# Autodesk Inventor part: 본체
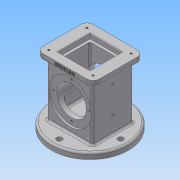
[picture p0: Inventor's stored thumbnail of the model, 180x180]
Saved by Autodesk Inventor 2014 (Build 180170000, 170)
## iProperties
Created: 2018-10
Part Number: 본체
Material: Generic
Document SubType Name: Modeling
Designer: Administrator
Density: 1 g/cm^3
Appearance: Default
Author: Administrator
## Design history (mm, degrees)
sketch "스케치1"
  geometry: C1 r 62.5 at (0, 0); 1 further point
  constraints: 1 centre point, 1 coincident
  dimensions: "d0" = 125 diameter of C1
extrude "돌출1" new body sketch "스케치1" distance "d1" = 10; taper "d2" = 0 deg
sketch "스케치2"
  geometry: L1 (-37, 33)-(37, 33); L2 (37, 33)-(37, -33); L3 (37, -33)-(-37, -33); L4 (-37, -33)-(-37, 33); L5 (-37, 33)-(37, -33); L6 (37, 33)-(-37, -33); C1 r 62.5 at (0, 0) reference
  constraints: 12 end point, 2 midpoint, 2 parallel, 1 horizontal, 1 perpendicular
  dimensions: "d3" = 74 distance of L2.end L3.end; "d4" = 66 distance of L1.end L2.end
extrude "돌출2" join sketch "스케치2" distance "d5" = 98; taper "d6" = 0 deg
sketch "스케치3"
  geometry: L1 (37, 33)-(-37, 33) reference; L2 (-37, 33)-(-37, -33) reference; L3 (-37, -33)-(37, -33) reference; L4 (37, -33)-(37, 33) reference; L5 (-46, 41)-(46, 41); L6 (46, 41)-(46, -41); L7 (46, -41)-(-46, -41); L8 (-46, -41)-(-46, 41); L9 (-46, 41)-(46, -41); L10 (46, 41)-(-46, -41); 1 further point
  constraints: 12 end point, 2 midpoint, 2 parallel, 1 horizontal, 1 perpendicular
  dimensions: "d7" = 92 distance of L6.end L7.end; "d8" = 82 distance of L5.end L6.end
extrude "돌출3" join sketch "스케치3" distance "d9" = 10; taper "d10" = 0 deg
sketch "스케치6"
  geometry: L1 (-25.5, -10)-(99.5, -10) reference; C1 r 35 at (37, 44); 2 further points
  constraints: 1 centre point, 1 midpoint, 1 vertical alignment
  dimensions: "d19" = 70 diameter of C1; "d20" = 54 distance from line of L1 C1.centre
extrude "돌출6" cut sketch "스케치6" distance "d21" = 3; taper "d22" = 0 deg
sketch "스케치7"
  geometry: C1 r 35 at (0, 0) reference; C2 r 24 at (0, 0); 1 further point
  constraints: 1 centre point, 1 coincident
  dimensions: "d23" = 48 diameter of C2
extrude "돌출7" cut sketch "스케치7" stored distance "d24" = 10; taper "d25" = 0 deg
sketch "스케치8"
  geometry: L1 (-26, 26)-(26, 26); L2 (26, 26)-(26, -26); L3 (26, -26)-(-26, -26); L4 (-26, -26)-(-26, 26); L5 (-26, 26)-(26, -26); L6 (26, 26)-(-26, -26); 1 further point
  constraints: 12 end point, 2 midpoint, 2 parallel, 1 horizontal, 1 perpendicular
  dimensions: "d26" = 52 distance of L2.end L3.end; "d27" = 52 distance of L1.end L2.end
extrude "돌출8" cut sketch "스케치8" distance "d28" = 8; taper "d29" = 0 deg
sketch "스케치9"
  geometry: L1 (-22, 22)-(22, 22); L2 (22, 22)-(22, -22); L3 (22, -22)-(-22, -22); L4 (-22, -22)-(-22, 22); L5 (-22, 22)-(22, -22); L6 (22, 22)-(-22, -22); 1 further point
  constraints: 12 end point, 2 midpoint, 2 parallel, 1 horizontal, 1 perpendicular
  dimensions: "d30" = 44 distance of L2.end L3.end; "d31" = 44 distance of L1.end L2.end
extrude "돌출9" cut sketch "스케치9" distance "d32" = 74; taper "d33" = 0 deg
sketch "스케치10"
  geometry: L1 (0, 0)-(-28, 0); L2 (-28, 0)-(-24.874, 17.727); L3 (-24.874, 17.727)-(0, 17.727); L4 (0, 17.727)-(0, 0)
  constraints: 8 end point, 1 horizontal, 1 parallel, 1 perpendicular
  dimensions: "d34" = 28 distance of L1.start L1.end; "d35" = 18 distance of L1.end L2.end; "d36" = 80 deg angle of L1 L2
revolve "회전1" sketch "스케치10" stored, may be unused: angle "d37" = 90 deg
fillet "모깎기1" dims "d38" = 3
fillet "모깎기2" dims "d39" = 3
fillet "모깎기3" dims "d40" = 3
fillet "모깎기4" dims "d41" = 10
fillet "모깎기5" dims "d42" = 3
chamfer "모따기1" distance "d43" = 1; stored, may be unused: second distance "d44" = 2, angle "d45" = 45 deg
fillet "모깎기6" dims "d46" = 3
fillet "모깎기7" dims "d47" = 3
fillet "모깎기8" dims "d48" = 3
fillet "모깎기9" dims "d49" = 3
sketch "스케치11"
  geometry: A1 r 10 centre (-36, 31) between (-36, 41) and (-46, 31) reference; A2 r 10 centre (-36, -31) between (-46, -31) and (-36, -41) reference; A3 r 10 centre (36, -31) between (36, -41) and (46, -31) reference; A4 r 10 centre (36, 31) between (46, 31) and (36, 41) reference; 5 further points
  constraints: 4 coincident
hole "구멍1" sketch "스케치11" at (-36, 31), (36, 31), (36, -31), (-36, -31) diameter "d50" = 3.242; stored, may be unused: countersink angle "d54" = 90 deg, drill point angle "d56" = 118 deg; dims "d51" = 4, "d52" = 4, "d53" = 2, "d55" = 6
sketch "스케치12"
  geometry: C1 r 24 at (0, 0) reference; 2 further points
  constraints: 1 vertical alignment
  dimensions: "d57" = 29 distance of C1.centre point (0, 29)
hole "구멍2" sketch "스케치12" at (0, 29) diameter "d58" = 3.242; stored, may be unused: countersink angle "d62" = 90 deg, drill point angle "d64" = 118 deg; dims "d59" = 4, "d60" = 4, "d61" = 2, "d63" = 6
node "작업축1"
sketch "스케치13"
  geometry: L1 (13, -32.5)-(13, 92.5) reference; 4 further points
  constraints: 2 horizontal alignment, 1 midpoint
  dimensions: "d68" = 37 distance from line of L1 point (-24, 30); "d69" = 43 distance of point (-67, 30) point (-24, 30)
hole "구멍3" sketch "스케치13" at (-24, 30), (-67, 30) diameter "d70" = 4.134; stored, may be unused: countersink angle "d74" = 90 deg, drill point angle "d76" = 118 deg; dims "d71" = 4, "d72" = 4, "d73" = 2, "d75" = 30
sketch "스케치14"
  geometry: L1 (72, 0)-(0, 0) reference; L2 (-10, 0)-(-10, -7) reference; 2 further points
  constraints: 1 other
  dimensions: "d77" = 4 distance from line of L1 point (36, -4); "d78" = 46 distance from line of L2 point (36, -4)
feature "엠보싱1" sketch "스케치14" dims "d79" = 0.5, "d80" = 0
sketch "스케치15"
  geometry: C1 r 59.5 at (0, 0) reference; C2 r 4.5 at (-50, 0); C3 r 4.5 at (50, 0)
  constraints: 2 centre point, 2 horizontal alignment
  dimensions: "d83" = 9 diameter of C2; "d84" = 9 diameter of C3; "d85" = 50 distance of C1.centre C2.centre; "d86" = 50 distance of C3.centre C1.centre
extrude "돌출10" cut sketch "스케치15" distance "d87" = 74; taper "d88" = 0 deg
sketch "스케치16"
  geometry: C1 r 59.5 at (0, 0) reference; C2 r 4.5 at (0, 50); C3 r 4.5 at (0, -50)
  constraints: 2 centre point, 2 vertical alignment
  dimensions: "d89" = 9 diameter of C2; "d90" = 9 diameter of C3; "d91" = 50 distance of C1.centre C2.centre; "d92" = 50 distance of C1.centre C3.centre
extrude "돌출11" cut sketch "스케치16" stored distance "d93" = 74; taper "d94" = 0 deg
node "솔리드1"
mirror "대칭1"
pattern_circular "원형 패턴1" dims angle "d66" = 360 deg
mirror "대칭2"
